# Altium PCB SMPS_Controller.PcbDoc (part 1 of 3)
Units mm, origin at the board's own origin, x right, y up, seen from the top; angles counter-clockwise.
Board outline 157 x 106 mm, 2 copper layers (Top Layer, Bottom Layer); 245 components, 175 nets, 948 pads, 171 vias.
Unrouted connection lines stored in the file: 2.
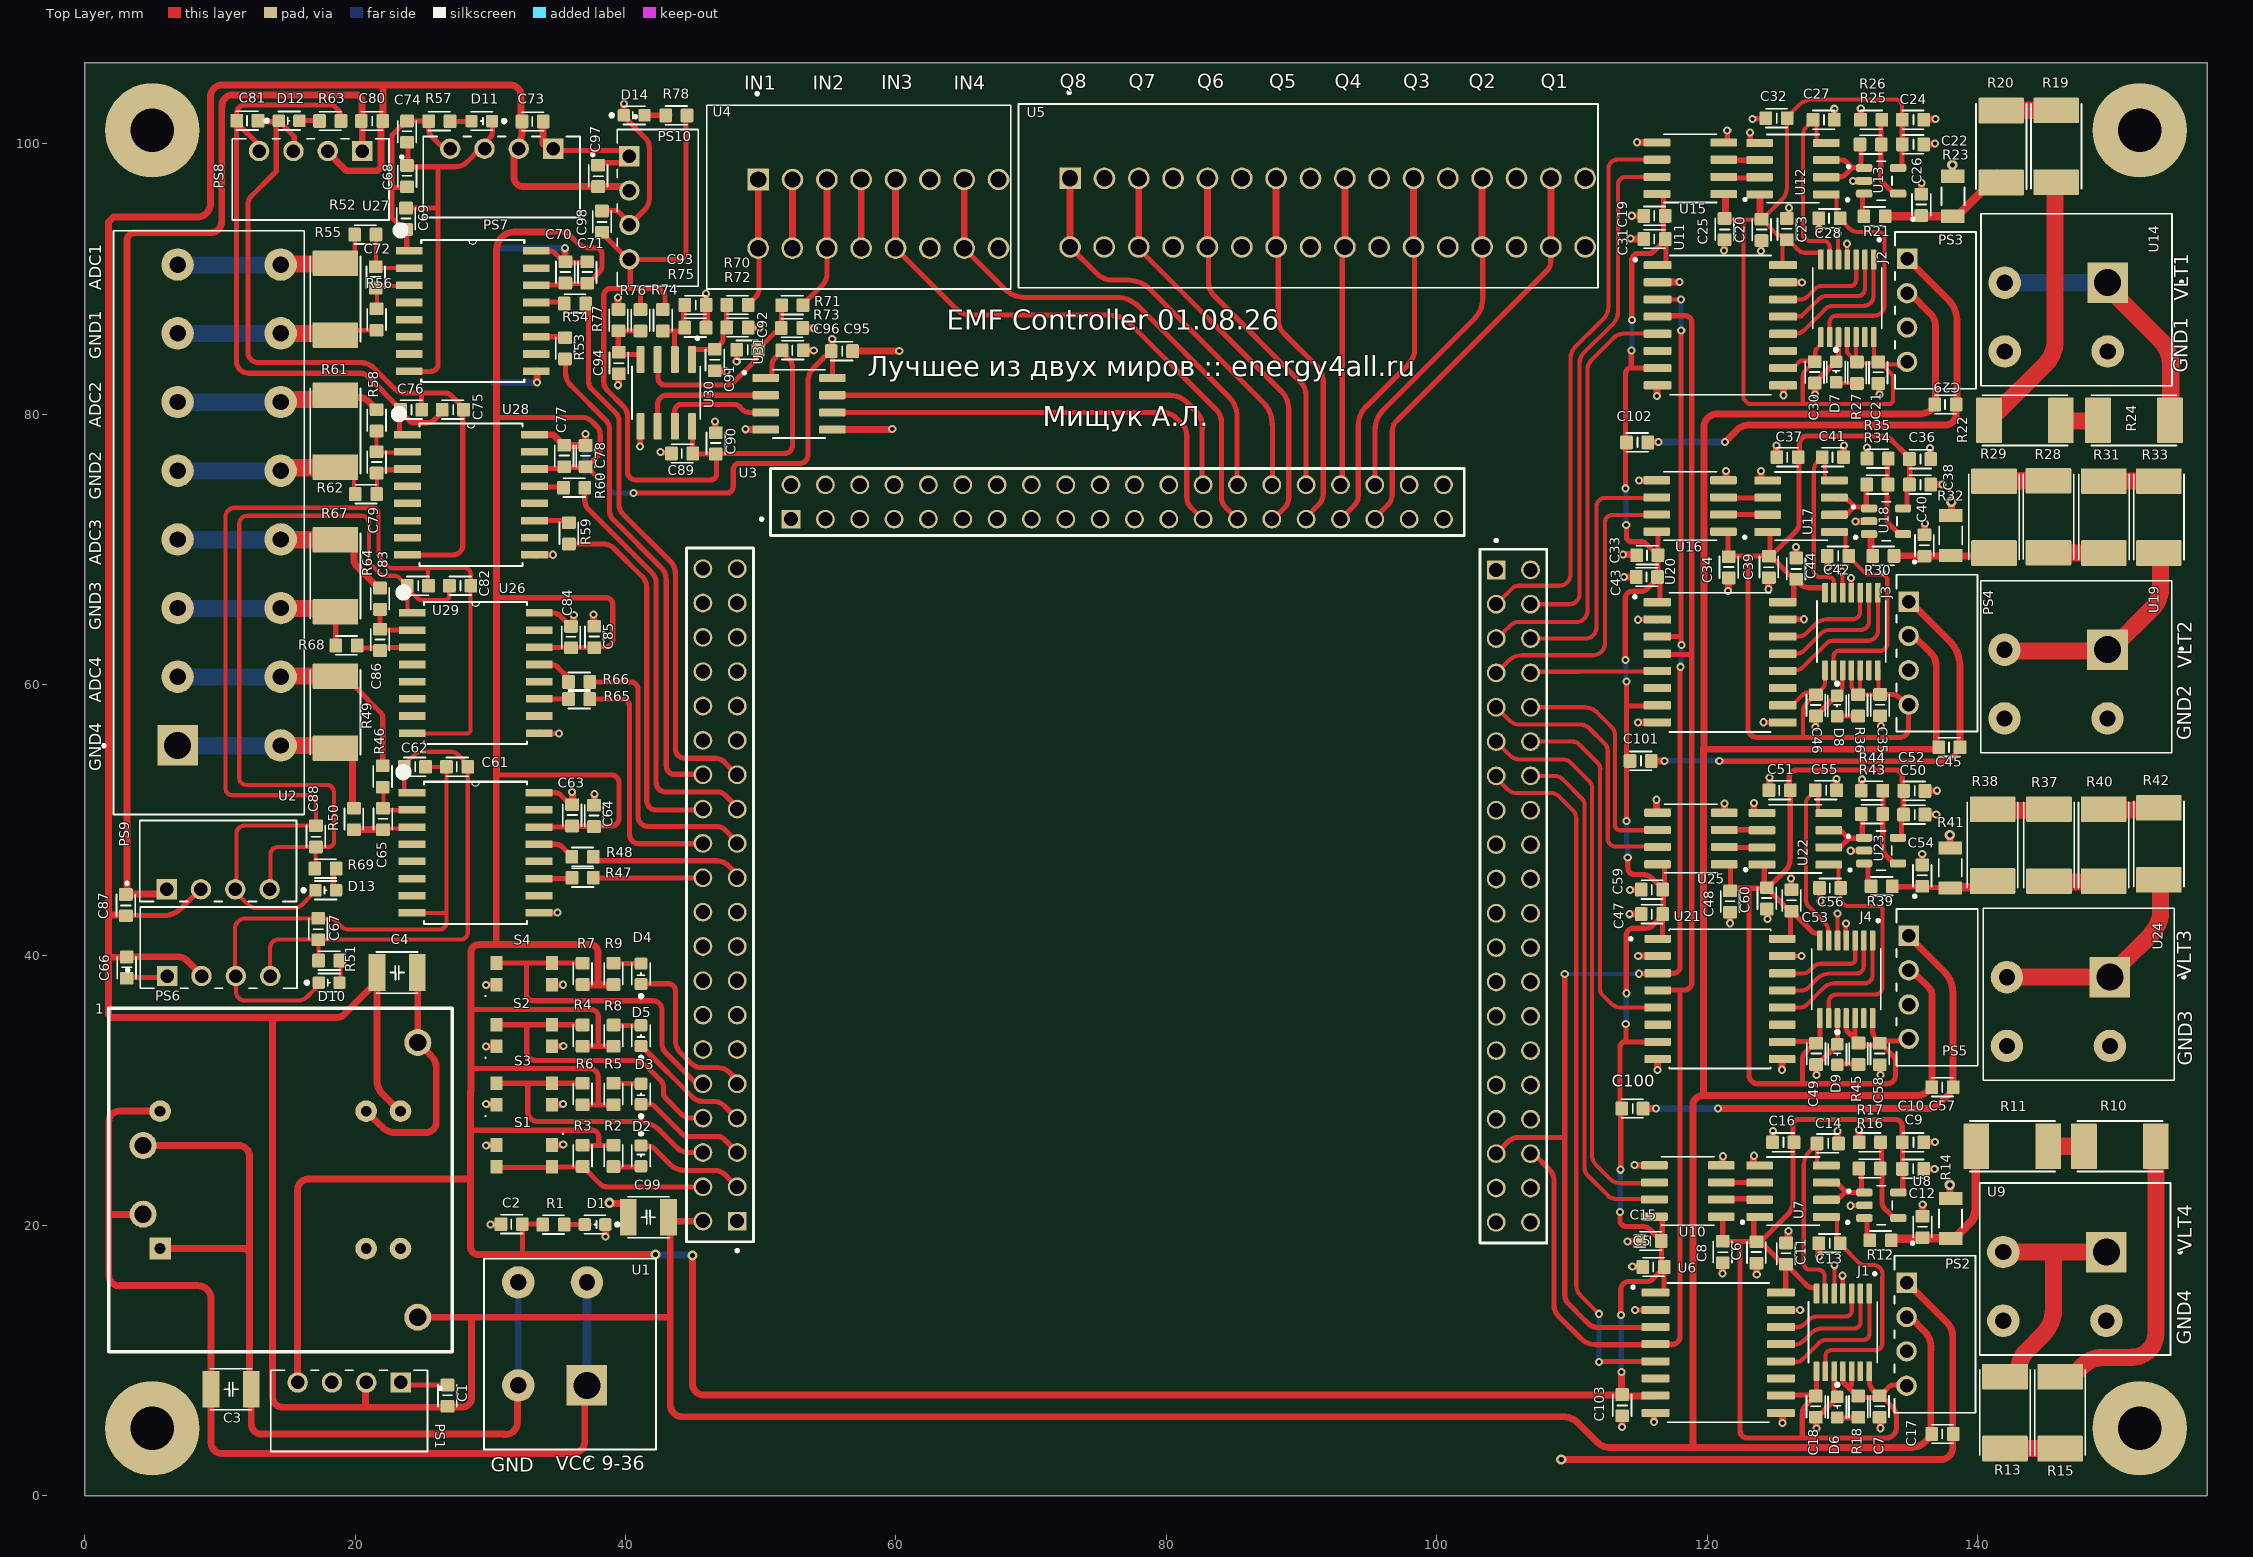
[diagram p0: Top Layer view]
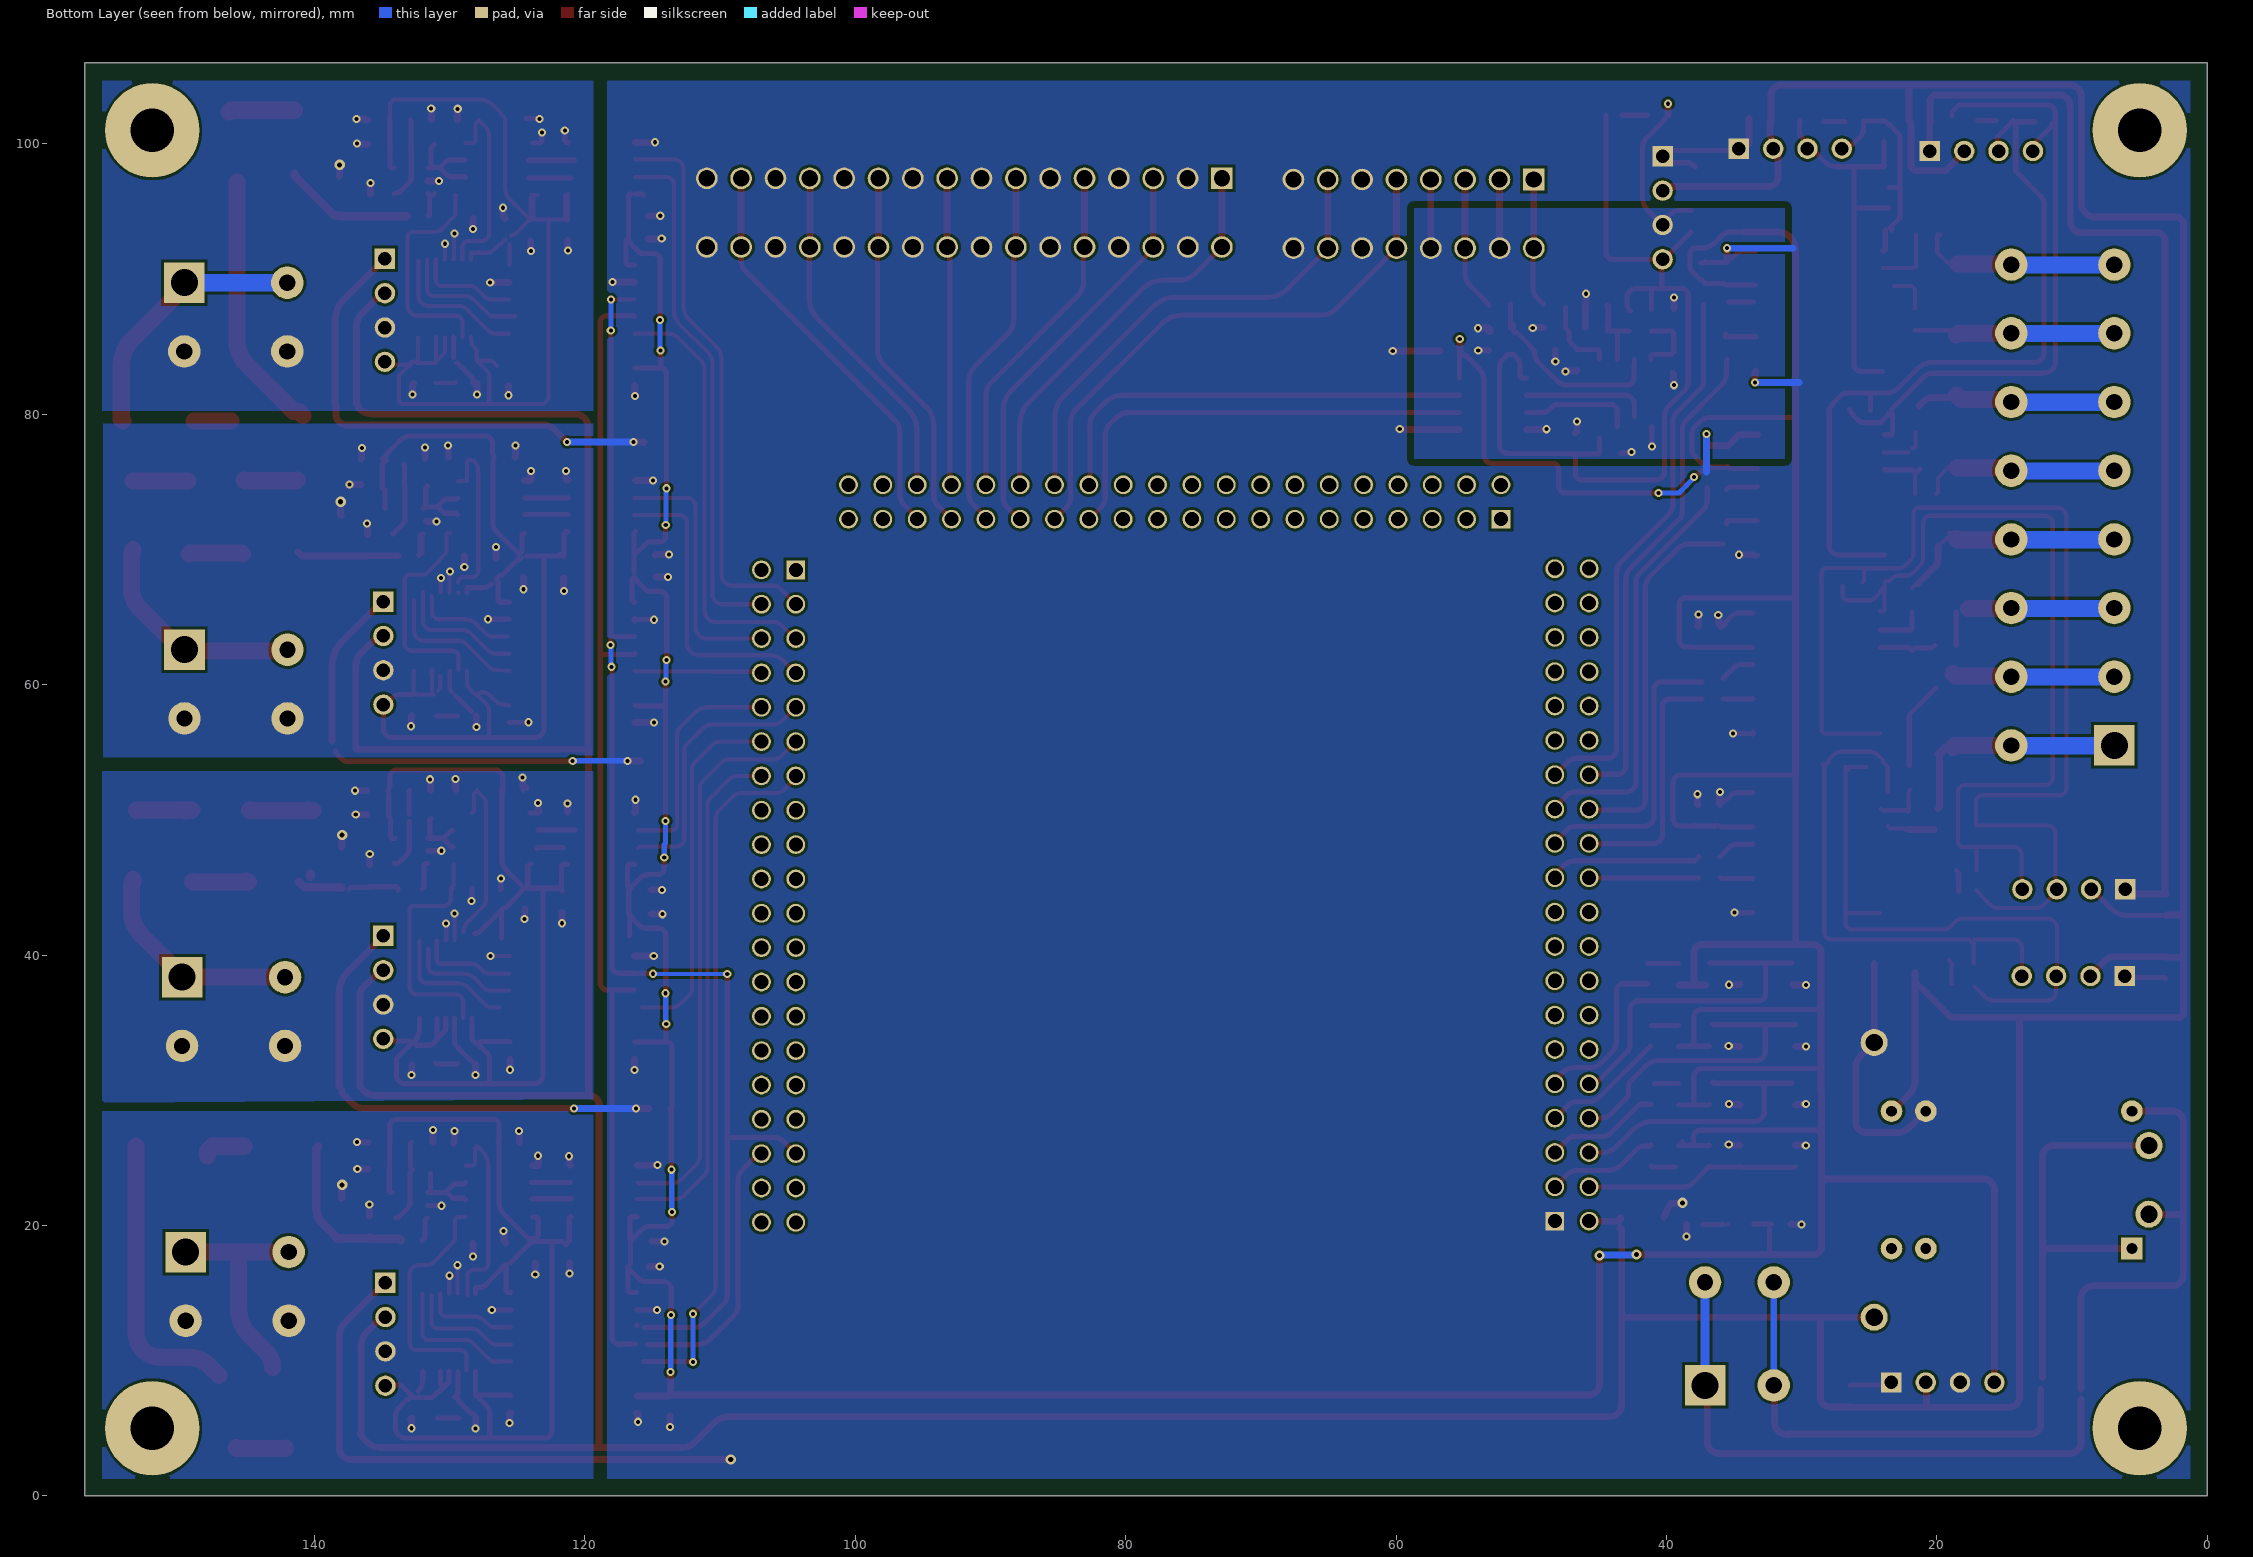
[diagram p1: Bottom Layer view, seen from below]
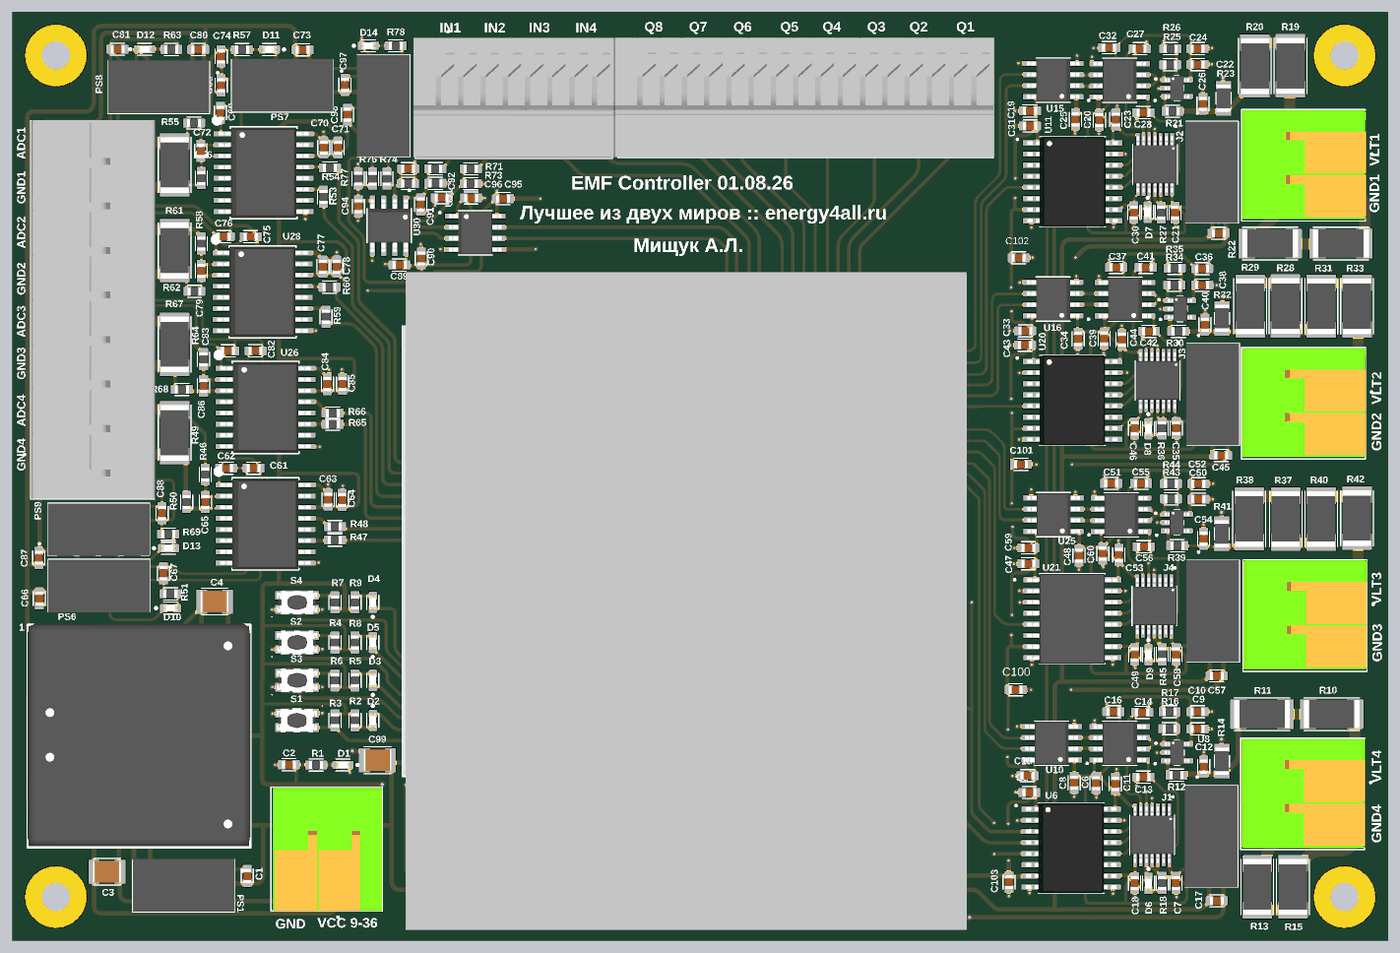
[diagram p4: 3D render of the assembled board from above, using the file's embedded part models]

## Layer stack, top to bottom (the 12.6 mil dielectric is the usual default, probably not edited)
Top Solder: solder mask 0.0102, Solder Resist, Dk 3.5
Top Layer: signal copper 0.0356
Dielectric 1: dielectric 0.32, FR-4, Dk 4.8
Bottom Layer: signal copper 0.0356
Bottom Solder: solder mask 0.0102, Solder Resist, Dk 3.5

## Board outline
0,0 0,106 157,106 157,0

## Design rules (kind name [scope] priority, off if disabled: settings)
Clearance [All] p1: gap=0.2 ignorepadtopadclearanceinfootprint=FALSE except(0: Arc-Hole Track-Hole SMDPad-Hole THPad-Hole Via-Hole Fill-Hole Poly-Hole Region-Hole Text-Hole; 0.152: Arc-Arc Arc-Track Arc-SMDPad Arc-THPad Arc-Via Track-Track Track-SMDPad Track-THPad Track-Via SMDPad-SMDPad SMDPad-THPad SMDPad-Via; 0.173: THPad-THPad; 0.5: Fill-Fill Fill-Poly Fill-Region Poly-Poly Poly-Region Region-Region)
Height [All] p1: minheight=0.254 maxheight=50.8 prefheight=25.4
HoleSize [All] p1: absolutevalues=TRUE maxlimit=7.62 minlimit=0.025 maxpercent=80.000 minpercent=20.000
MinimumSolderMaskSliver [All] p1 off: minsoldermaskwidth=0.254
PasteMaskExpansion [All] p1 off: expansion=0
PolygonConnect [All] p1: connectstyle=Direct reliefconductorwidth=0.254 reliefentries=4 polygonreliefangle="90 Angle" airgapwidth=0.254
RoutingVias [All] p1: holewidth=0.711 width=1.27 viastyle="Through Hole" minholewidth=0.711 minwidth=1.27 maxholewidth=0.711 maxwidth=1.27
SilkToSilkClearance [All] p1 off: silktosilkclearance=0.127
SilkToSolderMaskClearance [IsPad] p1 off: minsilkscreentomaskgap=0.254 clearancetoexposedcopper=TRUE
SolderMaskExpansion [All] p1 off: expansion=0.102 istentingtop=FALSE
SolderMaskExpansion SolderMaskExpansion_1 [All] p2: expansion=0.102 istentingtop=FALSE
SupplyNets "Schematic Supply Nets_24" [InNet('SIG_5V')] p1: voltage=0.000
SupplyNets "Schematic Supply Nets_22" [InNet('SIG_GND')] p2: voltage=0.000
SupplyNets "Schematic Supply Nets_21" [InNet('AGND_ISO3')] p3: voltage=0.000
SupplyNets "Schematic Supply Nets_18" [InNet('5V0_ISO3')] p4: voltage=0.000
SupplyNets "Schematic Supply Nets_17" [InNet('AGND_ISO4')] p5: voltage=0.000
SupplyNets "Schematic Supply Nets_16" [InNet('5V0_ISO4')] p6: voltage=0.000
SupplyNets "Schematic Supply Nets_15" [InNet('5V0_ISO2')] p7: voltage=0.000
SupplyNets "Schematic Supply Nets_14" [InNet('AGND_ISO2')] p8: voltage=0.000
SupplyNets "Schematic Supply Nets_20" [InNet('5V0_ISO1')] p9: voltage=0.000
SupplyNets "Schematic Supply Nets_19" [InNet('AGND_ISO1')] p10: voltage=0.000
SupplyNets "Schematic Supply Nets_13" [InNet('VLT3_5V')] p11: voltage=0.000
SupplyNets "Schematic Supply Nets_12" [InNet('3V3')] p12: voltage=0.000
SupplyNets "Schematic Supply Nets_11" [InNet('5V0')] p13: voltage=0.000
SupplyNets "Schematic Supply Nets_10" [InNet('VLT4_5V')] p14: voltage=0.000
SupplyNets "Schematic Supply Nets_9" [InNet('VLT2_5V')] p15: voltage=0.000
SupplyNets "Schematic Supply Nets_8" [InNet('VCC_9-36V')] p16: voltage=0.000
SupplyNets "Schematic Supply Nets_6" [InNet('VLT1_5V')] p17: voltage=0.000
SupplyNets "Schematic Supply Nets_5" [InNet('VLT4_GND')] p18: voltage=0.000
SupplyNets "Schematic Supply Nets_4" [InNet('VLT1_GND')] p19: voltage=0.000
SupplyNets "Schematic Supply Nets_3" [InNet('VLT3_GND')] p20: voltage=0.000
SupplyNets "Schematic Supply Nets_2" [InNet('VLT2_GND')] p21: voltage=0.000
SupplyNets "Schematic Supply Nets_1" [InNet('GND_3V3')] p22: voltage=0.000
Width [All] p1: maxlimit=2.794 minlimit=0.254 preferedwidth=0.508
24 further rules are at their usual default settings.

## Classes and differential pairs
component class SMPS_Signal: 23 C89 C90 C91 C92 C93 C94 C95 C96 C97 C98 D14 PS10 R70 R71 R72 R73 R74 R75 R76 R77 R78 U30 U31
component class SMPS_ADC_4: C61 C62 C63 C64 C65 C66 C67 D10 PS6 R46 R47 R48 R49 R50 R51 TP1 TP3 U26
component class SMPS_ADC_2: C75 C76 C77 C78 C79 C80 C81 D12 PS8 R58 R59 R60 R61 R62 R63 TP1 TP2 U28
component class SMPS_ADC_1: C68 C69 C70 C71 C72 C73 C74 D11 PS7 R52 R53 R54 R55 R56 R57 TP3 TP4 U27
component class SMPS_ADC_3: C82 C83 C84 C85 C86 C87 C88 D13 PS9 R64 R65 R66 R67 R68 R69 TP5 TP6 U29
component class SMPS_Voltage_4: C5 C6 C7 C8 C9 C10 C11 C12 C13 C14 C15 C16 C17 C18 D6 J1 PS2 R10 R11 R12 R13 R14 R15 R16 R17 R18 U6 U7 U8 U9 U10
component class SMPS_Voltage_2: C33 C34 C35 C36 C37 C38 C39 C40 C41 C42 C43 C44 C45 C46 D8 J3 PS4 R28 R29 R30 R31 R32 R33 R34 R35 R36 U16 U17 U18 U19 U20
component class SMPS_Voltage_1: C19 C20 C21 C22 C23 C24 C25 C26 C27 C28 C29 C30 C31 C32 D7 J2 PS3 R19 R20 R21 R22 R23 R24 R25 R26 R27 U11 U12 U13 U14 U15
component class SMPS_Voltage_3: C47 C48 C49 C50 C51 C52 C53 C54 C55 C56 C57 C58 C59 C60 D9 J4 PS5 R37 R38 R39 R40 R41 R42 R43 R44 R45 U21 U22 U23 U24 U25
component class SMPS_Supply: 1 C1 C2 C3 C4 C100 C101 C102 C103 D1 PS1 R1 U1
component class SMPS_Connector: C99 D2 D3 D4 D5 R2 R3 R4 R5 R6 R7 R8 R9 S1 S2 S3 S4 U2 U3 U4 U5

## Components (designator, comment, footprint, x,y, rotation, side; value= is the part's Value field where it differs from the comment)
1 "HLK-10D2412" HLK-10D2412 14.478,23.368 r0 top
C1 "4.7uF" CAP_0603 26.829,7.406 r90 top
C2 "4.7uF" CAP_0603 31.579,20.091 r180 top
C3 "47uF" CAP_1210 10.832,7.882 r180 top
C4 "47uF" CAP_1210 23.106,38.697 r180 top
C5 "0.1uF" CAP_0603 116.038,16.926 r180 top
C6 "0.1uF" CAP_0603 123.649,18 r90 top
C7 "0.1uF" CAP_0603 132.763,6.601 r90 top
C8 "2.2uF" CAP_0603 121.155,18.031 r270 top
C9 "2.2uF" CAP_0603 135.236,24.179 r0 top
C10 "0.1uF" CAP_0603 135.237,26.146 r0 top
C11 "0.1uF" CAP_0603 125.842,17.912 r90 top
C12 "1nF" CAP_0603 135.932,19.884 r90 top
C13 "10nF" CAP_0603 129.056,18.679 r0 top
C14 "10nF" CAP_0603 128.929,26.064 r0 top
C15 "0.1uF" CAP_0603 115.822,18.846 r180 top
C16 "0.1uF" CAP_0603 125.636,26.146 r0 top
C17 "10uF" CAP_0603 137.414,4.572 r180 top
C18 "10uF" CAP_0603 128.044,6.59 r90 top
C19 "0.1uF" CAP_0603 116.11,94.671 r180 top
C20 "0.1uF" CAP_0603 124.033,93.632 r90 top
C21 "0.1uF" CAP_0603 132.663,83.069 r90 top
C22 "2.2uF" CAP_0603 135.238,99.959 r0 top
C23 "2.2uF" CAP_0603 125.897,93.692 r90 top
C24 "0.1uF" CAP_0603 135.238,101.775 r0 top
C25 "0.1uF" CAP_0603 121.296,93.692 r270 top
C26 "1nF" CAP_0603 135.846,95.482 r90 top
C27 "0.1uF" CAP_0603 128.627,101.775 r0 top
C28 "0.1uF" CAP_0603 129.052,94.49 r180 top
C29 "10uF" CAP_0603 137.633,80.719 r180 top
C30 "10uF" CAP_0603 127.96,83.092 r90 top
C31 "0.1uF" CAP_0603 116.115,92.96 r180 top
C32 "0.1uF" CAP_0603 125.139,101.895 r0 top
C33 "0.1uF" CAP_0603 115.579,69.575 r180 top
C34 "0.1uF" CAP_0603 121.606,68.677 r90 top
C35 "0.1uF" CAP_0603 132.796,58.485 r90 top
C36 "2.2uF" CAP_0603 135.757,76.682 r0 top
C37 "2.2uF" CAP_0603 125.953,76.822 r180 top
C38 "0.1uF" CAP_0603 135.757,74.794 r0 top
C39 "0.1uF" CAP_0603 124.572,68.705 r270 top
C40 "1nF" CAP_0603 136.075,70.292 r90 top
C41 "10nF" CAP_0603 129.304,76.822 r180 top
C42 "10nF" CAP_0603 129.684,69.523 r0 top
C43 "0.1uF" CAP_0603 115.547,67.957 r180 top
C44 "0.1uF" CAP_0603 126.591,68.581 r270 top
C45 "10uF" CAP_0603 137.922,55.372 r180 top
C46 "10uF" CAP_0603 128.051,58.462 r90 top
C47 "0.1uF" CAP_0603 115.928,43.023 r180 top
C48 "0.1uF" CAP_0603 121.702,43.956 r90 top
C49 "0.1uF" CAP_0603 128.066,32.683 r90 top
C50 "2.2uF" CAP_0603 135.327,50.383 r0 top
C51 "2.2uF" CAP_0603 125.37,52.189 r180 top
C52 "0.1uF" CAP_0603 135.328,52.141 r0 top
C53 "0.1uF" CAP_0603 126.244,44.034 r90 top
C54 "1nF" CAP_0603 135.915,45.873 r90 top
C55 "0.1uF" CAP_0603 128.786,52.189 r0 top
C56 "0.1uF" CAP_0603 129.105,44.961 r180 top
C57 "10uF" CAP_0603 137.414,30.226 r180 top
C58 "10uF" CAP_0603 132.775,32.682 r90 top
C59 "0.1uF" CAP_0603 115.928,44.837 r180 top
C60 "0.1uF" CAP_0603 124.42,44.185 r90 top
C61 "0.1uF" CAP_0603 27.544,53.92 r180 top
C62 "10uF" CAP_0603 24.422,53.917 r0 top
C63 "0.1uF" CAP_0603 36.051,50.333 r90 top
C64 "10uF" CAP_0603 37.667,50.291 r90 top
C65 "1nf" CAP_0603 22.058,50.059 r90 top
C66 "10uF" CAP_0603 3.107,39.065 r90 top
C67 "10uF" CAP_0603 17.27,41.927 r270 top
C68 "0.1uF" CAP_0603 23.844,97.606 r90 top
C69 "10uF" CAP_0603 23.764,94.457 r90 top
C70 "0.1uF" CAP_0603 35.553,90.498 r90 top
C71 "10uF" CAP_0603 37.171,90.488 r90 top
C72 "1nf" CAP_0603 21.526,90.122 r90 top
C73 "10uF" CAP_0603 33.132,101.647 r180 top
C74 "10uF" CAP_0603 23.842,100.899 r90 top
C75 "0.1uF" CAP_0603 27.232,80.337 r0 top
C76 "10uF" CAP_0603 24.148,80.337 r0 top
C77 "0.1uF" CAP_0603 35.464,76.914 r90 top
C78 "10uF" CAP_0603 37.048,76.903 r90 top
C79 "1nf" CAP_0603 21.59,76.437 r90 top
C80 "10uF" CAP_0603 21.248,101.684 r0 top
C81 "10uF" CAP_0603 12.032,101.713 r180 top
C82 "0.1uF" CAP_0603 27.771,67.312 r0 top
C83 "10uF" CAP_0603 24.638,67.31 r0 top
C84 "0.1uF" CAP_0603 35.97,63.516 r90 top
C85 "10uF" CAP_0603 37.688,63.527 r90 top
C86 "1nf" CAP_0603 21.844,63.307 r90 top
C87 "10uF" CAP_0603 3.046,43.692 r270 top
C88 "10uF" CAP_0603 17.102,48.778 r270 top
C89 "2.2uF" CAP_0603 44.188,77.095 r180 top
C90 "0.1uF" CAP_0603 46.682,77.845 r90 top
C91 "16pF" CAP_0603 46.606,84.01 r90 top
C92 "16pF" CAP_0603 49.017,84.764 r0 top
C93 "0.1uF" CAP_0603 45.179,88.077 r0 top
C94 "0.1uF" CAP_0603 39.509,83.79 r270 top
C95 "0.1uF" CAP_0603 56.006,84.667 r0 top
C96 "0.1uF" CAP_0603 52.36,84.737 r180 top
C97 "10uF" CAP_0603 37.974,97.629 r270 top
C98 "10uF" CAP_0603 38.26,94.245 r270 top
C99 "47uF" CAP_1210 41.688,20.6 r0 top
C100 "0.1uF" CAP_0603 114.476,28.643 r0 top
C101 "0.1uF" CAP_0603 115.086,54.356 r0 top
C102 "0.1uF" CAP_0603 114.829,77.916 r0 top
C103 "0.1uF" CAP_0603 113.723,6.7 r270 top
D1 "led_0603" led_0603 37.747,20.067 r180 top
D2 "led_0603" led_0603 41.148,25.146 r270 top
D3 "led_0603" led_0603 41.148,29.718 r90 top
D4 "led_0603" led_0603 41.148,34.036 r90 top
D5 "led_0603" led_0603 41.148,38.608 r90 top
D6 "led_0603" led_0603 129.629,6.557 r270 top
D7 "led_0603" led_0603 129.54,83.122 r270 top
D8 "led_0603" led_0603 129.614,58.42 r270 top
D9 "led_0603" led_0603 129.638,32.642 r270 top
D10 "led_0603" led_0603 18.081,37.957 r0 top
D11 "led_0603" led_0603 29.368,101.684 r180 top
D12 "led_0603" led_0603 15.118,101.704 r0 top
D13 "led_0603" led_0603 17.835,44.791 r0 top
D14 "led_0603" led_0603 40.64,102.108 r0 top
J1 "MCP42010-E/SL" SOP65P640X120-14N 130.045,12.081 r270 top
J2 "MCP42010-E/SL" SOP65P640X120-14N 130.37,88.568 r270 top
J3 "MCP42010-E/SL" SOP65P640X120-14N 130.675,63.927 r270 top
J4 "MCP42010-E/SL" SOP65P640X120-14N 130.296,38.202 r270 top
PS1 "B0503S-1WR3" B0503S-1W 19.558,6.282 r180 top
PS2 "B0505S-1WR3" B0503S-1W 136.857,11.951 r270 top
PS3 "B0505S-1WR3" B0503S-1W 136.893,87.682 r270 top
PS4 "B0505S-1WR3" B0503S-1W 137.01,62.329 r270 top
PS5 "B0505S-1WR3" B0503S-1W 137.018,37.606 r270 top
PS6 "B0505S-1WR3" B0503S-1W 9.911,40.545 r0 top
PS7 "B0505S-1WR3" B0503S-1W 30.842,97.543 r180 top
PS8 "B0505S-1WR3" B0503S-1W 16.71,97.367 r180 top
PS9 "B0505S-1WR3" B0503S-1W 9.868,46.956 r0 top
PS10 "B0505S-1WR3" B0503S-1W 42.388,95.267 r270 top
R1 "10K" RESC1608X50N 34.679,20.059 r180 top
R2 "10K" RESC1608X50N 39.116,25.146 r90 top
R3 "10K" RESC1608X50N 36.83,25.146 r90 top
R4 "10K" RESC1608X50N 36.83,34.036 r270 top
R5 "10K" RESC1608X50N 39.116,29.718 r270 top
R6 "10K" RESC1608X50N 36.83,29.718 r270 top
R7 "10K" RESC1608X50N 36.83,38.608 r270 top
R8 "10K" RESC1608X50N 39.116,34.036 r270 top
R9 "10K" RESC1608X50N 39.116,38.608 r270 top
R10 "430K" RES_2512 150.535,25.853 r0 top
R11 "430K" RES_2512 142.58,25.853 r0 top
R12 "10K" RESC1608X50N 132.83,18.898 r0 top
R13 "430K" RES_2512 146.111,6.156 r90 top
R14 "10K" RES_1206 138.012,20.504 r270 top
R15 "430K" RES_2512 142.037,6.156 r270 top
R16 "NC" RESC1608X50N 132.019,24.204 r0 top
R17 "NC" RESC1608X50N 132.044,26.146 r180 top
R18 "10K" RESC1608X50N 131.187,6.597 r90 top
R19 "430K" RES_2512 145.824,99.822 r270 top
R20 "430K" RES_2512 141.762,99.8 r90 top
R21 "10K" RESC1608X50N 132.381,94.639 r0 top
R22 "430K" RES_2512 143.51,79.544 r180 top
R23 "10K" RES_1206 138.186,96.122 r270 top
R24 "430K" RES_2512 151.582,79.544 r180 top
R25 "NC" RESC1608X50N 132.102,99.945 r0 top
R26 "NC" RESC1608X50N 132.141,101.775 r180 top
R27 "10K" RESC1608X50N 131.09,83.069 r90 top
R28 "430K" RES_2512 145.253,72.414 r270 top
R29 "430K" RES_2512 141.224,72.39 r90 top
R30 "10K" RESC1608X50N 133.04,69.523 r0 top
R31 "430K" RES_2512 149.352,72.39 r270 top
R32 "10K" RES_1206 138.022,71.017 r270 top
R33 "430K" RES_2512 153.416,72.39 r90 top
R34 "0R" RESC1608X50N 132.594,74.794 r0 top
R35 "NC" RESC1608X50N 132.622,76.715 r180 top
R36 "10K" RESC1608X50N 131.174,58.466 r90 top
R37 "430K" RES_2512 145.292,48.127 r270 top
R38 "430K" RES_2512 141.115,48.131 r90 top
R39 "10K" RESC1608X50N 132.917,45.086 r0 top
R40 "430K" RES_2512 149.334,48.127 r270 top
R41 "10K" RES_1206 137.989,46.448 r270 top
R42 "430K" RES_2512 153.416,48.223 r90 top
R43 "0R" RESC1608X50N 132.205,50.42 r0 top
R44 "NC" RESC1608X50N 132.202,52.157 r180 top
R45 "10K" RESC1608X50N 131.197,32.696 r90 top
R46 "22R" RESC1608X50N 22.041,53.2 r270 top
R47 "22R" RESC1608X50N 36.83,45.72 r180 top
R48 "22R" RESC1608X50N 36.822,47.263 r180 top
R49 "0.5R" RES_2512 18.542,57.959 r90 top
R50 "22R" RESC1608X50N 19.91,50.059 r270 top
R51 "10K" RESC1608X50N 18.081,39.586 r180 top
R52 "22R" RESC1608X50N 20.755,93.287 r0 top
R53 "22R" RESC1608X50N 35.532,84.874 r90 top
R54 "22R" RESC1608X50N 36.264,88.18 r180 top
R55 "0.5R" RES_2512 18.542,88.512 r90 top
R56 "22R" RESC1608X50N 21.59,87.007 r90 top
R57 "10K" RESC1608X50N 26.236,101.674 r180 top
R58 "22R" RESC1608X50N 21.59,79.545 r270 top
R59 "22R" RESC1608X50N 35.814,71.189 r90 top
R60 "22R" RESC1608X50N 36.2,74.566 r180 top
R61 "0.5R" RES_2512 18.542,78.746 r90 top
R62 "22R" RESC1608X50N 20.801,74.092 r0 top
R63 "10K" RESC1608X50N 18.161,101.684 r0 top
R64 "22R" RESC1608X50N 21.844,66.349 r270 top
R65 "22R" RESC1608X50N 36.576,58.928 r180 top
R66 "22R" RESC1608X50N 36.576,60.198 r180 top
R67 "0.5R" RES_2512 18.542,68.045 r90 top
R68 "22R" RESC1608X50N 19.363,62.898 r0 top
R69 "10K" RESC1608X50N 17.812,46.392 r180 top
R70 "510R" RESC1608X50N 48.28,88.076 r180 top
R71 "510R" RESC1608X50N 52.338,88.065 r180 top
R72 "1000K" RESC1608X50N 48.288,86.417 r0 top
R73 "1000K" RESC1608X50N 52.321,86.377 r0 top
R74 "4K7" RESC1608X50N 42.758,86.948 r270 top
R75 "1K" RESC1608X50N 45.17,86.406 r0 top
R76 "4K7" RESC1608X50N 41.111,86.948 r270 top
R77 "1K" RESC1608X50N 39.478,86.958 r90 top
R78 "10K" RESC1608X50N 43.759,102.102 r0 top
S1 "KMR231GLFS" KMR231GLFS 32.512,25.146 r0 top
S2 "KMR231GLFS" KMR231GLFS 32.512,34.036 r180 top
S3 "KMR231GLFS" KMR231GLFS 32.512,29.718 r180 top
S4 "KMR231GLFS" KMR231GLFS 32.512,38.608 r180 top
U1 "DG142R-5.08-02P" DG142R-5.08-02P 32.07,15.788 r0 top
U2 "DG142R-5.08-10P" DG142R-5.08-10P 10.684,73.283 r270 top
U3 "LGA506" AC7020C 108.332,1.157 r90 top
U4 "DG141R-2.54-08P" DG141R-2.54-08P 67.595,97.361 r180 top
U5 "DG141R-2.54-16P" DG141R-2.54-16P 90.666,97.449 r180 top
U6 "ISO7240DW" ISO7240DW 120.824,10.582 r0 top
U7 "TLV3502AID" TLV3502AID 126.36,22.529 r180 top
U8 "OPA735AIDR" OPA735AIDBVR 132.892,21.49 r0 top
U9 "DG142R-5.08-02P" DG142R-5.08-02P 141.914,12.947 r90 top
U10 "ISO7220MDR" ISO7220MDR 118.58,22.544 r180 top
U11 "ISO7240DW" ISO7240DW 120.982,86.584 r0 top
U12 "TLV3502AID" TLV3502AID 126.356,98.163 r180 top
U13 "OPA735AIDR" OPA735AIDBVR 132.875,97.267 r0 top
U14 "DG142R-5.08-02P" DG142R-5.08-02P 142.013,84.649 r90 top
U15 "ISO7220MDR" ISO7220MDR 118.766,98.188 r180 top
U16 "ISO7220MDR" ISO7220MDR 118.749,73.211 r180 top
U17 "TLV3502AID" TLV3502AID 126.953,73.196 r180 top
U18 "OPA735AIDR" OPA735AIDBVR 133.241,72.085 r0 top
U19 "DG142R-5.08-02P" DG142R-5.08-02P 141.999,57.502 r90 top
U20 "ISO7240DW" ISO7240DW 120.96,61.649 r0 top
U21 "" SI8641ED 120.95,36.748 r0 top
U22 "TLV3502AID" TLV3502AID 126.532,48.593 r180 top
U23 "OPA735AIDR" OPA735AIDBVR 132.869,47.721 r0 top
U24 "DG142R-5.08-02P" DG142R-5.08-02P 142.176,33.277 r90 top
U25 "ISO7220MDR" ISO7220MDR 118.808,48.619 r180 top
U26 "AD7401AYRWZ" AD7401AYRWZ 28.906,47.557 r0 top
U27 "AD7401AYRWZ" AD7401AYRWZ 28.702,87.63 r0 top
U28 "AD7401AYRWZ" AD7401AYRWZ 28.575,74.041 r0 top
U29 "AD7401AYRWZ" AD7401AYRWZ 28.92,60.854 r0 top
U30 "TLV3502AID" TLV3502AID 43.014,81.576 r270 top
U31 "ISO7220MDR" ISO7220MDR 52.832,80.772 r0 top

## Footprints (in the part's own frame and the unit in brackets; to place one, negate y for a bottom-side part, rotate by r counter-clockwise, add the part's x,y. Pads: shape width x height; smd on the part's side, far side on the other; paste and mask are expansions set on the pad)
AC7020C [mm]
  round 1.39 hole 1.04 mask+0.102: 34(26.69,1.388) A02(19.157,62.608) A03(21.697,60.068) A04(21.697,62.608) A05(24.237,60.068) A06(24.237,62.608) A07(26.777,60.068) A08(26.777,62.608) A09(29.317,60.068) A10(29.317,62.608) A11(31.857,60.068) A12(31.857,62.608) A13(34.397,60.068) A14(34.397,62.608) A15(36.937,60.068) A16(36.937,62.608) A17(39.477,60.068) A18(39.477,62.608) A19(42.017,60.068) A20(42.017,62.608) A21(44.557,60.068) A22(44.557,62.608) A23(47.097,60.068) A24(47.097,62.608) A25(49.637,60.068) A26(49.637,62.608) A27(52.177,60.068) A28(52.177,62.608) A29(54.717,60.068) A30(54.717,62.608) A31(57.257,60.068) A32(57.257,62.608) A33(59.797,60.068) A34(59.797,62.608) A35(62.337,60.068) A36(62.337,62.608) A37(64.877,60.068) A38(64.877,62.608) A39(67.417,60.068) A40(67.417,62.608) B02(73.622,56.087) B03(71.082,53.547) B04(73.622,53.547) B05(71.082,51.007) B06(73.622,51.007) B07(71.082,48.467) B08(73.622,48.467) B09(71.082,45.927) B10(73.622,45.927) B11(71.082,43.387) B12(73.622,43.387) B13(71.082,40.847) B14(73.622,40.847) B15(71.082,38.307) B16(73.622,38.307) B17(71.082,35.767) B18(73.622,35.767) B19(71.082,33.227) B20(73.622,33.227) B21(71.082,30.687) B22(73.622,30.687) B23(71.082,28.147) B24(73.622,28.147) B25(71.082,25.607) B26(73.622,25.607) B27(71.082,23.067) B28(73.622,23.067) B29(71.082,20.527) B30(73.622,20.527) B31(71.082,17.987) B32(73.622,17.987) B33(71.082,15.447) B34(73.622,15.447) B35(71.082,12.907) B36(73.622,12.907) B37(71.082,10.367) B38(73.622,10.367) B39(71.082,7.827) B40(73.622,7.827) C2(41.93,1.388) C02(67.33,1.388) C03(64.79,3.928) C04(64.79,1.388) C05(62.25,3.928) C06(62.25,1.388) C07(59.71,3.928) C08(59.71,1.388) C09(57.17,3.928) C10(57.17,1.388) C11(54.63,3.928) C12(54.63,1.388) C13(52.09,3.928) C14(52.09,1.388) C15(49.55,3.928) C16(49.55,1.388) C17(47.01,3.928) C18(47.01,1.388) C19(44.47,3.928) C20(44.47,1.388) C21(41.93,3.928) C23(39.39,3.928) C24(39.39,1.388) C25(36.85,3.928) C26(36.85,1.388) C27(34.31,3.928) C28(34.31,1.388) C29(31.77,3.928) C30(31.77,1.388) C31(29.23,3.928) C32(29.23,1.388) C33(26.69,3.928) C35(24.15,3.928) C36(24.15,1.388) C37(21.61,3.928) C38(21.61,1.388) C39(19.07,3.928) C40(19.07,1.388)
  rect 1.39x1.39 / inner round 1.39 / far side rect 1.39x1.39 hole 1.04 mask+0.102: A01(19.157,60.068) B01(71.082,56.087) C01(67.33,3.928)
  silkscreen extent 16.88,0.18 74.83,63.81, body extent 0.11,-0.55 75.11,63.85, height 22.64
AD7401AYRWZ [mil]
  rect 78x22 smd: 1(-185,175) 2(-185,125) 3(-185,75) 4(-185,25) 5(-185,-25) 6(-185,-75) 7(-185,-125) 8(-185,-175) 9(185,-175) 10(185,-125) 11(185,-75) 12(185,-25) 13(185,25) 14(185,75) 15(185,125) 16(185,175)
  silkscreen extent -214,-207 150,239, body extent -204,-203 203,203, height 104
B0503S-1W [mm]
  rect 1.508x1.508 hole 1: 1(-3.81,-2.1)
  round 1.508 hole 1: 2(-1.27,-2.1) 3(1.27,-2.1) 4(3.81,-2.1)
  silkscreen extent -6.84,-3 5.8,3, body extent -5.8,-3.05 5.8,2.95, height 10.1
CAP_0603 [mm]
  rrect20% 0.94x1.02 smd: 1(-0.79,0) 2(0.79,0)
  silkscreen extent -0.8,-0.69 0.8,0.69, body extent -0.81,-0.45 0.79,0.45, height 0.81
CAP_1210 [mm]
  rect 1.24x2.73 smd: 1(-1.485,0) 2(1.485,0)
  silkscreen extent -1.52,-1.52 1.52,1.52, body extent -1.6,-1.24 1.6,1.26, height 1.97
DG141R-2.54-08P [mm]
  rect 1.6x1.6 hole 1.2: 1(17.78,0)
  round 1.6 hole 1.2: 1(17.78,5.08) 2(15.24,0) 2(15.26,5.08) 3(12.7,0) 3(12.7,5.08) 4(10.16,0) 4(10.16,5.08) 5(7.62,0) 5(7.62,5.08) 6(5.08,5.08) 6(5.08,0) 7(2.54,5.08) 7(2.54,0) 8(0,5.08) 8(0,0)
  silkscreen extent -0.9,-6.45 21.59,8.1, body extent -1.07,-5.64 21.79,7.96, height 12.6
DG141R-2.54-16P [mm]
  rect 1.6x1.6 hole 1.2: 1(17.78,0)
  round 1.6 hole 1.2: 1(17.78,5.08) 2(15.24,0) 2(15.26,5.08) 3(12.7,0) 3(12.7,5.08) 4(10.16,0) 4(10.16,5.08) 5(7.62,0) 5(7.62,5.08) 6(5.08,5.08) 6(5.08,0) 7(2.54,5.08) 7(2.54,0) 8(0,5.08) 8(0,0) 9(-2.54,5.08) 9(-2.54,0) 10(-5.08,5.08) 10(-5.08,0) 11(-7.62,0) 11(-7.62,5.08) 12(-10.16,0) 12(-10.16,5.08) 13(-12.7,0) 13(-12.7,5.08) 14(-15.24,0) 14(-15.24,5.08) 15(-17.78,0) 15(-17.78,5.08) 16(-20.32,0) 16(-20.32,5.08)
  silkscreen extent -21.26,-6.45 21.59,8.1, body extent -21.29,-5.58 21.89,8.02, height 12.6
DG142R-5.08-02P [mm]
  rect 3x3 hole 2: 1(5.08,-7.62)
  round 2.4 hole 1.2: 1(5.08,0) 2(0,-7.62) 2(0,0)
  silkscreen extent -2.54,-13.18 10.19,1.75, body extent -2.29,-12.41 10.11,1.69, height 13.43
DG142R-5.08-10P [mm]
  rect 3x3 hole 2: 1(17.78,-3.81)
  round 2.4 hole 1.2: 1(17.78,3.81) 2(12.7,-3.81) 2(12.7,3.81) 3(7.62,-3.81) 3(7.62,3.81) 4(2.54,3.81) 4(2.54,-3.81) 5(-2.54,3.81) 5(-2.54,-3.81) 6(-7.62,-3.81) 6(-7.62,3.81) 7(-12.7,-3.81) 7(-12.7,3.81) 8(-17.78,-3.81) 8(-17.78,3.81)
  silkscreen extent -20.29,-9.37 22.89,5.56, body extent -20.32,-8.47 22.86,5.64, height 13.52
HLK-10D2412 [mm]
  rect 1.6x1.6 hole 0.8: 1(-8.9,-5.08)
  round 1.6 hole 0.8: 7(6.34,-5.08) 8(8.88,-5.08) 9(8.88,5.08) 10(6.34,5.08) 16(-8.9,5.08)
  round 2 hole 1.28: 100(-10.16,2.54) 200(-10.16,-2.54) 300(10.16,-10.16) 500(10.16,10.16)
  silkscreen extent -12.7,-12.7 12.71,12.7, body extent -12.7,-12.57 12.7,12.83, height 11.7
ISO7220MDR [mm]
  rrect25% 1.97x0.6 smd: 1(-2.47,1.905) 2(-2.47,0.635) 3(-2.47,-0.635) 4(-2.47,-1.905) 5(2.47,-1.905) 6(2.47,-0.635) 7(2.47,0.635) 8(2.47,1.905)
  silkscreen extent -4.14,-2.52 1.95,2.52, body extent -3,-2.45 3,2.45, height 1.75
ISO7240DW [mm]
  rrect25% 2.06x0.6 smd: 1(-4.64,4.445) 2(-4.64,3.175) 3(-4.64,1.905) 4(-4.64,0.635) 5(-4.64,-0.635) 6(-4.64,-1.905) 7(-4.64,-3.175) 8(-4.64,-4.445) 9(4.64,-4.445) 10(4.64,-3.175) 11(4.64,-1.905) 12(4.64,-0.635) 13(4.64,0.635) 14(4.64,1.905) 15(4.64,3.175) 16(4.64,4.445)
  silkscreen extent -6.4,-5.15 3.75,5.15, body extent -5.16,-5.15 5.14,5.15, height 2.65
KMR231GLFS [mm]
  rect 0.9x1 smd: 1(2.05,0.8) 2(2.05,-0.8) 3(-2.05,0.8) 4(-2.05,-0.8)
  silkscreen extent 2.85,1.62 2.88,1.65, body extent -2.32,-1.4 2.28,1.4, height 1.9
led_0603 [mm]
  rrect25% 0.91x0.93 smd: A(0.76,0) C(-0.76,0)
  silkscreen extent -1.77,-0.68 0.8,0.68, body extent -0.8,-0.4 0.8,0.4, height 0.65
OPA735AIDBVR [mm]
  rrect50% 1.21x0.59 smd: 1(-1.255,0.95) 2(-1.255,0) 3(-1.255,-0.95) 4(1.255,-0.95) 5(1.255,0.95)
  silkscreen extent -2.51,-1.45 0.8,1.45, body extent -1.4,-1.45 1.4,1.45, height 1.45
RES_1206 [mm]
  rect 0.97x1.73 smd: 1(-1.48,0) 2(1.48,0)
  silkscreen extent -0.67,-0.85 0.67,0.85, body extent -1.55,-0.8 1.55,0.8, height 0.65
RES_2512 [mm]
  rrect7% 1.9x3.37 smd: 1(-2.66,0) 2(2.66,0)
  silkscreen extent -3.15,-1.87 3.15,1.87, body extent -3.17,-1.6 3.17,1.6, height 0.65
RESC1608X50N [mm]
  rrect20% 0.94x1.02 smd: 1(-0.79,0) 2(0.79,0)
  silkscreen extent -0.8,-0.69 0.8,0.69, body extent -0.79,-0.48 0.81,0.47, height 0.78
SI8641ED [mm]
  rrect25% 1.97x0.6 smd: 1(-4.605,4.445) 2(-4.605,3.175) 3(-4.605,1.905) 4(-4.605,0.635) 5(-4.605,-0.635) 6(-4.605,-1.905) 7(-4.605,-3.175) 8(-4.605,-4.445) 9(4.605,-4.445) 10(4.605,-3.175) 11(4.605,-1.905) 12(4.605,-0.635) 13(4.605,0.635) 14(4.605,1.905) 15(4.605,3.175) 16(4.605,4.445)
  silkscreen extent -6.69,-5.15 3.75,5.15, body extent -5.17,-5.18 5.13,5.12, height 2.65
SOP65P640X120-14N [mm]
  rrect25% 1.47x0.41 smd: 1(-2.87,1.95) 2(-2.87,1.3) 3(-2.87,0.65) 4(-2.87,0) 5(-2.87,-0.65) 6(-2.87,-1.3) 7(-2.87,-1.95) 8(2.87,-1.95) 9(2.87,-1.3) 10(2.87,-0.65) 11(2.87,0) 12(2.87,0.65) 13(2.87,1.3) 14(2.87,1.95)
  silkscreen extent -4.44,-2.55 2.25,2.55, body extent -3.22,-2.49 3.18,2.51, height 1.2
TLV3502AID [mm]
  rrect25% 1.97x0.6 smd: 1(-2.47,1.905) 2(-2.47,0.635) 3(-2.47,-0.635) 4(-2.47,-1.905) 5(2.47,-1.905) 6(2.47,-0.635) 7(2.47,0.635) 8(2.47,1.905)
  silkscreen extent -4.14,-2.52 1.95,2.52, body extent -3,-2.45 3,2.45, height 1.75

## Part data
1: "Isolated Module DC DC Converter Input: 9-24V   output: +12", Package="SIP-7 Tracopower"
C1 C2 C5 C6 C7 C8 C9 C10 C11 C12 C13 C14 C15 C16 C17 C18 C19 C20 C21 C22 C23 C24 C25 C26 C27 C28 C29 C30 C31 C32 C33 C34 C35 C36 C37 C38 C39 C40 C41 C42 C43 C44 C45 C46 C47 C48 C49 C50 C51 C52 C53 C54 C55 C56 C57 C58 C59 C60 C61 C62 C63 C64 C65 C66 C67 C68 C69 C70 C71 C72 C73 C74 C75 C76 C77 C78 C79 C80 C81 C82 C83 C84 C85 C86 C87 C88 C89 C90 C91 C92 C93 C94 C95 C96 C97 C98 C100 C101 C102 C103: library part CAP_0603
C3 C4 C99: library part CAP_1210
D1 D2 D3 D4 D5 D6 D7 D8 D9 D10 D11 D12 D13 D14: "LED Indication - Discrete 3.1V 0603 _1608 Metric_", Package="0603 Lite-On"
J1 J2 J3 J4: "DIGITAL POT, 256 STEPS, SPI, 10KOHMS, DUAL CHANNEL", Package="SOIC-14 Microchip"
PS1: library part B0505S-1WR3, "Isolated Module DC DC Converter 1 Output 5V 200mA 4.5V - 5.5V Input", Package="SIP-4-4 MORNSUN"
PS2 PS3 PS4 PS5 PS6 PS7 PS8 PS9 PS10: "Isolated Module DC DC Converter 1 Output 5V 200mA 4.5V - 5.5V Input", Package="SIP-4-4 MORNSUN"
R1 R2 R3 R4 R5 R6 R7 R8 R9 R12 R16 R17 R18 R21 R25 R26 R27 R30 R34 R35 R36 R39 R43 R44 R45 R46 R47 R48 R50 R51 R52 R53 R54 R56 R57 R58 R59 R60 R62 R63 R64 R65 R66 R68 R69 R70 R71 R72 R73 R74 R75 R76 R77 R78: library part RES_0603, "1% 0.1W", Package=None
R10 R11 R13 R15 R19 R20 R22 R24 R28 R29 R31 R33 R37 R38 R40 R42 R49 R55 R61 R67: library part RES_2512, "2512 1% 1W", Package=None
R14 R23 R32 R41: library part RES_1206, "1% 1/4W", Package=None
S1 S2 S3 S4: "Tactile Switch SPST-NO Top Actuated Surface Mount", Package=None
U1 U2 U4 U5 U9 U14 U19 U24: "DG129-5.0-03P-14-00AH"
U3: library part AC7020C
U6 U8 U11 U13 U18 U20 U23: Package=None
U7 U12 U17 U22 U30: "4.5ns Rail-to-Rail Comparator", Package="SOIC-8 Texas Instruments"
U10 U15 U16 U25 U31: "Dual-channel, 2/0, 150-Mbps digital isolator 8-SOIC -40 to 125", Package="SOIC-8 Texas Instruments"
U21: library part SI8641ED, "General Purpose Digital Isolator 2500Vrms 4 Channel 150Mbps 35kV/Âµs CMTI 16-SOIC _0.154, 3.90mm Width_", Package="SOIC-16 Silicon Labs"
U26 U27 U28 U29: library part AD7401YRWZ, "Isolated Module 16 b Serial 16-SOIC", Package="SOIC WIDE-16 Analog Devices"

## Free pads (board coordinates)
  round 7 hole 3.2: 3(5,5) 3(152,5) 3(152,101) 4(5,101)

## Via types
v1: diameter 0.6, hole 0.3, Top Layer to Bottom Layer, tented both sides, 163 vias
v2: diameter 0.762, hole 0.381, Top Layer to Bottom Layer, tented both sides, 8 vias

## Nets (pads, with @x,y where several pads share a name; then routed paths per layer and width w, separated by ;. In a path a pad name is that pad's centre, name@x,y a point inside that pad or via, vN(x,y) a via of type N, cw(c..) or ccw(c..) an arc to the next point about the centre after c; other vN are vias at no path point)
3V3: C2.1 C5.1 C15.1 C19.1 C31.1 C33.1 C43.1 C47.1 C59.1 C63.1 C64.1 C70.1 C71.1 C77.1 C78.1 C84.1 C85.1 C95.1 C100.1 C101.1 C102.1 C103.1 PS1.4 R1.2 R2.2 R3.2 R4.2 R5.2 R6.2 R7.2 R8.2 R9.2 U6.1 U6.7 U10.8 U11.1 U11.7 U15.8 U16.8 U20.1 U20.7 U21.1 U21.7 U25.8 U26.14 U27.14 U28.14 U29.14 U31.8 | length 477.2
  Top Layer w0.305: U20.7@116.265,58.42 U20.7@116.32,58.474
  Top Layer w0.381: 28.538,29.936 28.562,29.936 ; 28.562,31.605 37.34,31.605 cw(c37.34,30.959) 37.986,30.959 37.986,28.906 ; 28.562,35.956 37.471,35.956 cw(c37.471,35.438) 37.99,35.438 37.99,33.246 ; 28.812,27.034 37.535,27.034 cw(c37.535,26.549) 38.02,26.549 38.02,25.908 ; 30.442,53.324 30.454,53.324 38.948,53.324 cw(c38.948,52.755) 39.517,52.755 39.517,50.094 cw(c38.954,50.094) 38.954,49.532 38.024,49.532 37.952,49.603 37.952,49.608 37.863,49.518 37.859,49.522 36.371,49.522 C63.1@36.321,49.572 ; 30.48,79.756 36.833,79.756 cw(c36.833,78.846) 37.476,79.49 ; 30.543,66.422 38.573,66.422 cw(c38.573,65.943) 39.052,65.943 39.052,63.302 ; C2.1@32.258,20.101 R1.2@33.56,20.101 ; 32.391,17.842 C2.1@32.391,19.781 ; U28.14@33.274,75.946 33.307,75.979 35.32,75.979 C77.1@35.464,76.124 ; U27.14@33.418,89.552 35.639,89.552 C70.1@35.746,89.659 ; U26.14@33.608,49.464 35.972,49.464 C63.1@36.051,49.543 ; U29.14@33.635,62.743 C84.1@35.952,62.743 ; 34.29,93.472 35.305,93.472 cw(c35.305,92.636) 35.897,93.227 ; C77.1@35.468,76.12 35.509,76.079 C78.1@37.014,76.079 ; C70.1@35.749,89.659 C71.1@37.171,89.659 ; 35.896,93.226 36.51,92.611 ; C84.1@35.98,62.736 C85.1@37.687,62.736 ; 36.517,92.618 ccw(c37.274,93.375) 37.274,92.305 37.822,92.305 cw(c37.822,91.871) 38.256,91.871 ; R3.2@36.83,25.936 ccw(c36.898,26.004) 36.898,25.908 38.02,25.908 ; R6.2@36.83,28.968 R6.2@36.892,28.906 ; R4.2@36.83,33.246 37.99,33.246 ; C78.1@37.048,76.113 37.327,76.392 37.419,76.392 37.909,76.883 ; R7.2@37.084,37.818 R7.2@37.114,37.788 ; C78.1@37.084,75.946 37.367,75.833 v1(37.962,75.368) ; R6.2@37.094,28.906 37.986,28.906 ; C71.1@37.171,89.698 37.451,89.977 37.535,89.977 38.013,90.455 38.056,90.498 ccw(c37.54,91.013) 38.269,91.013 38.269,91.871 ; 37.48,79.493 37.892,79.081 cw(c37.311,78.5) 38.132,78.5 38.132,78.453 ; C85.1@37.688,62.737 38.007,62.773 38.528,62.773 ccw(c38.528,63.297) 39.052,63.301 ; 37.906,76.886 ccw(c37.352,77.44) 38.136,77.44 38.136,78.453 ; R2.2@38.834,26.19 R2.2@38.862,26.162 ; R9.2@39.086,37.788 R9.2@39.116,37.818 ; R5.2@39.094,28.906 37.986,28.906 ; R2.2@39.116,25.908 38.02,25.908 ; R8.2@39.116,33.246 37.99,33.246 ; v1@40.64,74.168 47.481,74.168 ccw(c47.481,74.656) 47.969,74.656 47.969,75.91 cw(c48.415,75.91) 48.415,76.357 52.878,76.357 ccw(c52.878,76.983) 53.504,76.983 53.504,82.493 cw(c54.692,82.493) 53.851,83.333 ; 53.839,83.346 54.84,84.348 54.937,84.348 55.216,84.627 C95.1@55.216,84.667 55.313,84.57 U31.8@55.313,82.688 ; v1(113.548,20.985) 113.548,20.384 ccw(c114.007,20.384) 114.007,19.925 115.217,19.925 cw(c115.217,19.134) 115.776,19.693 ; v1@113.619,24.142 113.619,28.576 C100.1@113.686,28.643 113.561,28.768 113.561,33.194 cw(c113.947,33.194) 113.947,33.58 ; v1(113.635,13.366) 113.617,13.384 113.617,15.248 cw(c114.224,15.248) 114.224,15.855 115.57,15.855 ccw(c115.57,16.403) 115.957,16.015 C5.1@116.616,16.674 ; v1(113.974,74.521) 113.974,74.62 113.977,74.622 113.977,83.021 ; 113.973,83.021 cw(c114.378,83.021) 114.378,83.426 U11.7@116.325,83.426 ; v1(113.979,61.833) 113.947,61.864 113.947,66.366 113.947,66.367 cw(c114.479,66.371) 114.479,66.903 115.162,66.903 ccw(c115.162,67.46) 115.555,67.066 116.067,67.578 116.067,67.638 116.346,67.972 116.522,67.796 116.522,66.204 116.413,66.094 U20.1@116.32,66.094 ; v1@114.009,34.866 114.009,33.635 113.947,33.573 U21.7@116.345,33.573 ; v1(114.024,71.817) 114.047,71.794 114.047,70.926 ccw(c114.404,70.926) 114.1,70.739 114.218,70.621 ccw(c114.404,70.926) 114.404,70.569 115.17,70.569 cw(c115.17,70.148) 115.468,70.445 116.019,69.894 116.09,69.894 C33.1@116.256,69.681 ; v1(114.037,49.917) 114.046,49.927 114.046,58.42 ; v1(114.045,60.219) 114.046,60.217 114.046,58.42 ; v1(114.048,37.173) 114.017,37.204 114.017,41.434 cw(c114.562,41.434) 114.562,41.979 115.449,41.979 ccw(c115.449,42.767) 116.007,42.21 116.438,42.641 116.438,42.704 C47.1@116.718,43.023 116.761,43.067 116.761,44.794 C59.1@116.718,44.837 116.438,45.157 116.028,45.567 ; 114.135,46.551 v1(114.135,47.217) ; 114.141,46.551 114.141,46.432 ccw(c114.628,46.432) 114.628,45.945 115.239,45.945 115.241,45.945 cw(c115.241,44.935) 116.027,45.568 ; 114.393,83.44 v1@114.393,84.703 ; v1@114.424,86.999 114.424,91.404 cw(c114.9,91.404) 114.9,91.88 115.667,91.88 ccw(c115.667,92.419) 116.048,92.038 116.625,92.615 116.625,92.68 C31.1@116.905,92.96 116.975,92.889 116.975,91.138 116.866,91.029 U11.1@116.342,91.029 ; U15.8@115.63,96.174 115.739,96.283 U15.8@116.296,96.283 ; 115.771,19.688 116.292,19.166 116.332,19.166 C15.1@116.612,18.846 ; U10.8@116.11,20.639 116.576,20.639 116.685,20.53 116.685,18.969 C15.1@116.614,18.898 ; U6.1@116.184,15.027 116.697,15.027 116.806,15.136 C5.1@116.806,16.905 ; U20.7@116.265,58.42 114.046,58.42 ; U16.8@116.279,71.306 116.369,71.217 116.369,69.769 C33.1@116.325,69.725 ; U25.8@116.338,46.714 116.731,46.714 116.84,46.604 C59.1@116.84,45.103 ; 116.345,68.672 116.354,68.663 116.371,68.663 C33.1@116.371,69.624 ; C43.1@116.371,68.292 116.371,68.719 ; U15.8@116.586,96.266 116.688,96.266 116.78,96.174 C31.1@116.78,92.96 ; C15.1@116.627,18.885 116.627,17.127 C5.1@116.828,16.926 ; U21.1@116.704,41.397 C47.1@116.704,42.969
  Top Layer w0.508: PS1.4@15.748,8.382 15.748,22.618 cw(c16.561,22.618) 16.561,23.431 ; 16.561,23.426 28.538,23.426 ; 28.538,29.936 28.538,23.426 ; 28.562,29.936 28.562,31.605 28.562,35.956 28.562,40.194 cw(c29.126,40.194) 29.037,40.75 29.208,40.778 cw(c29.289,40.276) 29.289,40.784 30.442,40.784 ; 30.442,53.324 30.442,40.784 ; 30.454,53.324 30.454,92.202 ; 30.48,92.202 cw(c31.75,92.202) 31.75,93.472 34.29,93.472 ; R7.2@37.114,37.788 37.963,37.788 ; R9.2@39.086,37.788 37.963,37.788 ; v2(42.224,17.842) 32.391,17.842 29.11,17.842 cw(c29.11,18.414) 28.538,18.414 28.538,23.426 ; v2(44.958,17.78) 44.958,8.278 ccw(c45.781,8.278) 45.781,7.456 C103.1@113.624,7.456 ; C95.1@55.216,84.667 55.276,84.727 55.276,85.54 v1(55.294,85.557) ; v1@113.679,9.145 113.679,7.533 113.841,7.372 U6.7@116.15,7.372 ; 30.442,40.784 37.377,40.784 cw(c37.377,40.198) 37.963,40.198 37.963,37.788
  Bottom Layer w0.381: v1(37.962,75.368) 37.962,75.309 38.543,74.728 38.543,74.707 39.071,74.179 v1(40.58,74.179) ; v1@113.55,21.037 113.574,21.06 113.574,24.096 v1(113.597,24.12) ; v1(113.635,13.366) 113.652,13.35 113.652,9.173 v1(113.668,9.157) ; v1(113.974,74.521) 113.999,74.496 113.999,71.898 v1@114.024,71.873 ; v1(113.979,61.833) 114.012,61.8 114.012,60.252 v1(114.045,60.219) ; v1(113.985,34.89) 114.017,34.921 114.017,37.141 v1(114.048,37.173) ; v1(114.037,49.917) 114.041,49.913 114.041,48.279 114.135,48.186 v1(114.135,47.217) ; v1(114.41,84.721) 114.442,84.752 v1(114.442,86.982)
  Bottom Layer w0.508: v2(42.224,17.842) 42.255,17.811 44.927,17.811 v2(44.958,17.78)
5V0: 1.9 1.300 C1.1 C4.2 C17.2 C29.2 C45.2 C57.2 C66.2 C73.2 C80.2 C87.2 C97.2 C99.2 PS1.2 PS2.2 PS3.2 PS4.2 PS5.2 PS6.2 PS7.2 PS8.2 PS9.2 PS10.2 U3.A02 | length 516.8
  Top Layer w0.381: C87.2@3.351,42.917 5.863,42.917 ccw(c5.863,44.683) 7.112,43.434 ; 7.115,43.431 8.54,44.856 PS9.2@8.598,44.856
  Top Layer w0.508: C87.2@3.046,42.902 2.982,42.966 1.765,42.966 ; C66.2@3.084,39.833 1.765,39.833 ; C66.2@3.126,39.874 6.904,39.874 cw(c6.904,38.995) 7.526,39.617 ; 7.529,39.62 8.641,38.508 PS6.2@8.641,38.445 ; 8.291,94.582 ccw(c8.291,95.598) 9.307,95.598 9.307,103.477 ; 8.291,94.584 2.141,94.584 1.765,94.207 1.765,42.966 ; 9.302,103.477 cw(c10.181,103.477) 10.181,104.356 22.068,104.356 ; PS8.2@17.684,99.693 19.372,98.004 21.619,98.004 21.917,98.302 21.917,101.562 C80.2@22.038,101.684 ; PS1.2@20.828,8.382 20.768,8.322 20.768,6.546 ; C4.2@21.621,38.697 C4.2@21.621,37.952 ; C80.2@22.068,101.714 22.068,104.356 ; 1.9@23.358,28.448 23.303,28.448 22.043,29.707 cw(c23.064,30.728) 21.621,30.728 C4.2@21.621,37.952 ; 1.300@24.384,13.208 28.613,13.208 ; 27.948,6.576 26.416,6.576 26.386,6.546 20.768,6.546 ; 27.948,6.58 ccw(c27.948,7.245) 28.613,7.245 28.613,13.208 ; PS7.2@31.75,99.636 31.75,97.536 ccw(c32.454,97.536) 32.454,96.832 C97.2@37.967,96.832 ; PS7.2@32.002,100.022 ccw(c31.167,100.858) 32.348,100.858 C73.2@32.348,101.647 ; C73.2@32.342,101.647 32.27,101.718 32.27,103.575 ccw(c31.489,103.575) 31.489,104.356 22.068,104.356 ; C97.2@37.977,96.836 40.064,96.836 ccw(c40.064,97.18) PS10.2@40.308,96.937 ; 43.236,13.264 43.18,13.208 28.613,13.208 ; C99.2@43.395,20.574 43.395,20.45 43.539,20.306 U3.A02@45.716,20.306 ; C99.2@43.434,19.812 43.315,19.693 43.315,6.743 ccw(c44.216,6.743) 44.216,5.842 109.376,5.842 109.379,5.842 cw(c109.378,4.338) 110.441,5.402 110.443,5.399 111.931,3.912 ccw(c112.737,4.715) 112.737,3.577 112.739,3.577 135.144,3.577 135.146,3.577 ccw(c135.146,4.931) 136.103,3.974 136.408,4.279 136.408,4.316 C17.2@136.632,4.565 ; 118.949,3.678 118.949,28.915 cw(c119.601,28.915) 119.601,29.567 ; 119.689,29.603 119.749,29.603 ; 119.749,55.322 119.749,55.221 ; 119.77,55.322 119.77,79.045 cw(c120.749,79.045) 120.749,80.024 135.385,80.024 135.732,80.024 ccw(c135.732,81.428) 136.642,80.358 C29.2@136.658,80.374 ; PS3.2@134.793,88.952 135.01,88.952 136.504,87.458 136.506,87.456 cw(c135.574,86.524) 136.892,86.524 C29.2@136.892,80.732 ; PS2.2@134.814,13.217 135.031,13.217 136.1,12.148 cw(c134.984,11.032) 136.562,11.032 136.562,10.747 ; PS4.2@134.874,63.754 135.136,63.754 136.553,62.337 cw(c135.6,61.384) 136.948,61.384 ; PS5.2@135.382,38.608 136.441,37.549 cw(c135.999,37.107) 136.624,37.107 136.624,30.482 C57.2@136.624,30.226 ; C57.2@136.42,30.006 136.407,29.994 cw(c135.464,30.937) 135.464,29.603 119.749,29.603 ; 136.549,10.747 136.549,4.647 C17.2@136.624,4.572 ; C29.2@136.658,80.374 136.729,80.446 136.736,80.463 C29.2@136.843,80.719 ; 136.952,61.384 136.952,55.257 136.916,55.221 119.749,55.221 ; 1.765,39.833 1.765,35.611 1.989,35.388 13.897,35.388 ; 1.765,39.833 1.765,42.966 ; 13.897,35.388 13.897,7.296 ccw(c14.646,7.296) 14.646,6.546 20.768,6.546 ; 13.897,35.388 18.708,35.388 ccw(c18.708,35.999) 19.14,35.567 21.159,37.586 21.255,37.586 C4.2@21.621,37.952 ; 119.749,29.603 119.749,55.221
5V0_ISO1: C68.1 C69.1 C74.2 PS7.4 R57.2 U27.1 | length 15
  Top Layer w0.381: 22.72,96.774 22.72,100.639 23.49,101.41 23.563,101.41 C74.2@23.842,101.689 ; C69.1@23.302,93.654 C69.1@23.356,93.6 ; C69.1@23.439,93.825 22.715,94.549 22.715,96.774 C68.1@23.582,96.774 ; C69.1@23.764,93.667 23.817,93.614 23.817,92.164 23.906,92.075 U27.1@24.003,92.075 ; C74.2@23.907,101.736 23.956,101.688 25.386,101.688 R57.2@25.423,101.651 ; R57.2@25.423,101.406 25.423,101.094 ccw(c26.163,101.094) 25.64,100.572 25.659,100.552 26.294,99.919 PS7.4@26.513,99.919
5V0_ISO2: C75.1 C76.1 C81.2 PS8.4 R63.2 U28.1 | length 49.4
  Top Layer w0.381: 11.225,102.252 cw(c11.844,102.252) 11.844,102.871 18.386,102.871 18.895,102.361 R63.2@18.895,102.067 ; 11.242,102.252 C81.2@11.242,101.713 ; PS8.4@12.7,99.568 12.684,99.584 12.684,100.127 11.522,101.289 11.522,101.434 C81.2@11.242,101.713 ; C76.1@23.34,80.395 20.952,82.783 20.95,82.784 ccw(c20.36,82.194) 20.361,83.029 20.359,83.029 12.124,83.029 cw(c12.124,83.934) 11.219,83.934 11.219,101.69 C81.2@11.242,101.713 ; U28.1@23.876,78.486 23.363,78.486 23.274,78.575 23.274,80.017 23.304,80.047 23.607,80.047 23.638,80.017 23.638,79.899 24.041,79.496 ; 24.033,79.488 ccw(c24.319,79.774) 24.319,79.369 25.361,79.369 ccw(c25.361,80.056) 25.847,79.57 ; 25.845,79.573 26.163,79.891 26.163,80.017 26.289,80.017 C75.1@26.442,80.337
